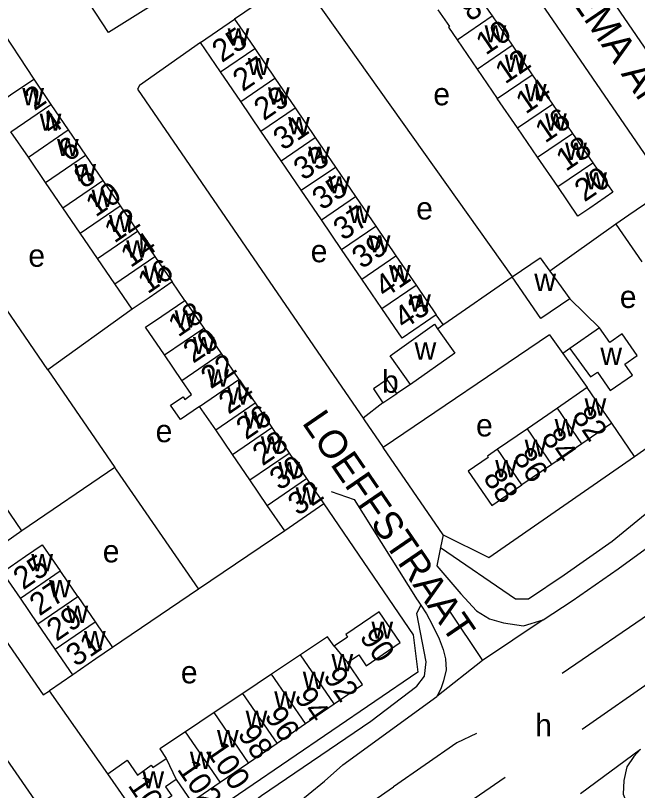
# Model space of a CAD drawing. Extents: x 157569 to 159501, y 382907 to 384670.
# Drawn here: x 158257.4 to 158368.1, y 383461.2 to 383599.1 of the extents above; entities that cross this region are included whole.
import ezdxf

# ---------------------------------------------------------------- set-up
doc = ezdxf.new("R2010")
doc.units = 0
for name, color, linetype in [('BLT_Basislijn', 7, 'Continuous'), ('BLT_Bebouwing', 7, 'Continuous'), ('BLT_Centroide', 7, 'Continuous'), ('BLT_Huisnummer', 7, 'Continuous'), ('BLT_Huisnummer_ tussenligend', 7, 'Continuous'), ('BLT_Onderverdeling_panden', 7, 'Continuous'), ('BLT_Straatnaam', 7, 'Continuous'), ('BLT_Vlakafsluiter', 7, 'Continuous')]:
    doc.layers.add(name, color=color, linetype=linetype)

msp = doc.modelspace()

# ---------------------------------------------------------------- linework, layer by layer
at = {"layer": 'BLT_Basislijn'}
for p, q in [((158334.91, 383624.76), (158373.53, 383568.42)), ((158307.74, 383606.23), (158296.41, 383598.5)), ((158307.74, 383606.23), (158345.82, 383552.61)), ((158252.74, 383599.87), (158260.65, 383587.83)), ((158263.17, 383536.11), (158238.22, 383572.51)), ((158364.3, 383561.98), (158352.53, 383553.62)), ((158287.58, 383548.44), (158285.31, 383551.74)), ((158361.4, 383543.55), (158356.07, 383548.71)), ((158278.2, 383546.88), (158263.17, 383536.11)), ((158333.55, 383544.13), (158332.31, 383545.87)), ((158332.56, 383543.37), (158333.55, 383544.13)), ((158352.49, 383542.32), (158322.88, 383522.28)), ((158352.49, 383542.32), (158354.86, 383539)), ((158356.1, 383539.87), (158354.86, 383539)), ((158354.86, 383539), (158359.19, 383532.93)), ((158367.58, 383520.65), (158393.72, 383538.95)), ((158263.17, 383536.11), (158275.07, 383518.71)), ((158327.71, 383533.47), (158325.28, 383531.9)), ((158316.13, 383532.05), (158319.31, 383527.48)), ((158322.82, 383530.23), (158319.31, 383527.48)), ((158367.58, 383520.65), (158363.56, 383526.58)), ((158333.54, 383506.73), (158322.88, 383522.28)), ((158341.65, 383502.68), (158367.58, 383520.65)), ((158275.07, 383518.71), (158258.57, 383507.41)), ((158312.33, 383512.22), (158328.23, 383488.92)), ((158305.33, 383507.44), (158290.01, 383497.05)), ((158333.54, 383506.73), (158341.65, 383502.68)), ((158290.01, 383497.05), (158274.71, 383486.68)), ((158334.55, 383493.34), (158340.54, 383484.37)), ((158371.55, 383493.55), (158354.72, 383482.03)), ((158379.21, 383486.63), (158358.27, 383472.09)), ((158267.62, 383481.82), (158263.44, 383478.98)), ((158273.85, 383464.21), (158263.44, 383478.98)), ((158268.87, 383411.85), (158344.6, 383463.62))]:
    msp.add_line(p, q, dxfattribs=at)
for points in [[(158402.62, 383683.14), (158349.23, 383647.01), (158287.55, 383604.67), (158273.97, 383596.14), (158266.09, 383608.24)], [(158351.55, 383636.27), (158344.49, 383631.24), (158343.9, 383630.57), (158382.66, 383574.03)], [(158290.34, 383594.36), (158279.47, 383586.68), (158279.15, 383586.02), (158316.13, 383532.05)], [(158333.55, 383544.13), (158333.69, 383544.24), (158345.82, 383552.61)], [(158333.08, 383504.49), (158346.41, 383495.33), (158348.71, 383495.33), (158355.09, 383499.59), (158363.6, 383505.61), (158370.16, 383510.93), (158376.37, 383516.61), (158381.86, 383521.93), (158400.39, 383534.72)], [(158319.31, 383527.48), (158319.49, 383527.21), (158322.88, 383522.28)], [(158275.07, 383518.71), (158275.35, 383518.3), (158290.01, 383497.05)], [(158313.62, 383514.43), (158317.72, 383513.01), (158328.92, 383495.17), (158328.95, 383495.12)], [(158351.37, 383491.6), (158356.51, 383494.97), (158364.67, 383500.65), (158373.39, 383507), (158376.46, 383509.13)], [(158333.54, 383506.73), (158333.08, 383504.49)], [(158333.08, 383504.49), (158332.4, 383501.18), (158336.66, 383496.22), (158339.49, 383493.2), (158341.8, 383491.78), (158344.28, 383491.07), (158347.83, 383490.54), (158351.37, 383491.6)], [(158247.46, 383499.74), (158247.67, 383499.43), (158262.36, 383478.24), (158263.44, 383478.98)], [(158285.33, 383447.86), (158288.45, 383450.24), (158293.8, 383454.7), (158296.92, 383457.08), (158301.23, 383460.35), (158320.69, 383473.57), (158328.86, 383479.81), (158330.2, 383481.6), (158330.5, 383484.12), (158328.86, 383492.74), (158329.57, 383494.21)], [(158328.95, 383495.12), (158329.57, 383494.21)], [(158328.95, 383495.12), (158328.97, 383495.07)], [(158329.57, 383494.21), (158330.59, 383492.69), (158331.58, 383490.76), (158332.82, 383488.24), (158333.56, 383486.3), (158333.96, 383484.67), (158334.06, 383482.69), (158333.61, 383480.76), (158333.12, 383479.32), (158332.42, 383477.98)], [(158328.23, 383488.92), (158329.02, 383482.29), (158283.13, 383450.96)], [(158284.53, 383441.35), (158292.81, 383446.92), (158296.69, 383450.16), (158303.7, 383455.76), (158312.43, 383462.88), (158315.66, 383465.79), (158332.42, 383477.98)], [(158251.08, 383470.55), (158252.5, 383471.5), (158264.68, 383454)], [(158339.47, 383471.34), (158335.98, 383469.7), (158324.71, 383461.89)], [(158368.7, 383468.6), (158367.49, 383467.29), (158366.26, 383465.41), (158365.68, 383463.03), (158365.61, 383460.57), (158366.26, 383458.9), (158367.85, 383456.37), (158370.74, 383452.03), (158372.62, 383449.93), (158373.85, 383448.78)], [(158262.9, 383417.82), (158318.11, 383457.34), (158324.71, 383461.89)]]:
    msp.add_lwpolyline(points, dxfattribs=at)
at = {"layer": 'BLT_Bebouwing'}
for p, q in [((158338.66, 383604.29), (158342.24, 383599.07)), ((158342.24, 383599.07), (158345.83, 383593.84)), ((158290.34, 383594.36), (158296.41, 383598.5)), ((158336.02, 383594.83), (158339.6, 383589.6)), ((158293.93, 383589.09), (158290.34, 383594.36)), ((158345.83, 383593.84), (158349.41, 383588.61)), ((158300, 383593.24), (158303.59, 383587.97)), ((158339.6, 383589.6), (158343.18, 383584.37)), ((158297.52, 383583.83), (158293.93, 383589.09)), ((158303.59, 383587.97), (158307.18, 383582.71)), ((158349.41, 383588.61), (158353, 383583.38)), ((158260.65, 383587.83), (158263.73, 383583.32)), ((158301.11, 383578.57), (158297.52, 383583.83)), ((158346.77, 383579.14), (158343.18, 383584.37)), ((158263.73, 383583.32), (158266.81, 383578.81)), ((158307.18, 383582.71), (158310.77, 383577.45)), ((158353, 383583.38), (158356.58, 383578.16)), ((158259.7, 383573.95), (158256.61, 383578.46)), ((158266.81, 383578.81), (158269.9, 383574.3)), ((158304.7, 383573.3), (158301.11, 383578.57)), ((158350.35, 383573.92), (158346.77, 383579.14)), ((158310.77, 383577.45), (158314.36, 383572.18)), ((158356.58, 383578.16), (158360.17, 383572.93)), ((158269.9, 383574.3), (158272.98, 383569.79)), ((158262.78, 383569.43), (158259.7, 383573.95)), ((158308.29, 383568.04), (158304.7, 383573.3)), ((158353.93, 383568.69), (158350.35, 383573.92)), ((158314.36, 383572.18), (158317.95, 383566.92)), ((158265.86, 383564.92), (158262.78, 383569.43)), ((158272.98, 383569.79), (158276.06, 383565.28)), ((158311.88, 383562.78), (158308.29, 383568.04)), ((158317.95, 383566.92), (158321.54, 383561.66)), ((158268.95, 383560.41), (158265.86, 383564.92)), ((158276.06, 383565.28), (158279.15, 383560.76)), ((158315.47, 383557.52), (158311.88, 383562.78)), ((158364.3, 383561.98), (158368.89, 383555.28)), ((158272.03, 383555.9), (158268.95, 383560.41)), ((158279.15, 383560.76), (158282.23, 383556.25)), ((158321.54, 383561.66), (158325.13, 383556.4)), ((158282.23, 383556.25), (158285.31, 383551.74)), ((158319.06, 383552.25), (158315.47, 383557.52)), ((158325.13, 383556.4), (158328.72, 383551.13)), ((158275.11, 383551.39), (158272.03, 383555.9)), ((158352.53, 383553.62), (158356.07, 383548.71)), ((158322.65, 383546.99), (158319.06, 383552.25)), ((158278.2, 383546.88), (158275.11, 383551.39)), ((158328.72, 383551.13), (158332.31, 383545.87)), ((158287.58, 383548.44), (158290.93, 383543.53)), ((158290.93, 383543.53), (158294.05, 383538.97)), ((158361.4, 383543.55), (158356.1, 383539.87)), ((158287.05, 383534.19), (158283.93, 383538.75)), ((158294.05, 383538.97), (158297.19, 383534.37)), ((158327.71, 383533.47), (158324.09, 383538.6)), ((158297.19, 383534.37), (158300.05, 383530.19)), ((158325.28, 383531.9), (158323.6, 383534.38)), ((158359.19, 383532.93), (158353.87, 383529.28)), ((158322.82, 383530.23), (158325.28, 383531.9)), ((158300.05, 383530.19), (158303.05, 383525.8)), ((158293.05, 383525.41), (158290.19, 383529.59)), ((158353.87, 383529.28), (158348.54, 383525.61)), ((158363.56, 383526.58), (158358.23, 383522.92)), ((158296.05, 383521.02), (158293.05, 383525.41)), ((158303.05, 383525.8), (158306.14, 383521.27)), ((158348.54, 383525.61), (158343.2, 383521.95)), ((158358.23, 383522.92), (158352.9, 383519.26)), ((158299.15, 383516.49), (158296.05, 383521.02)), ((158306.14, 383521.27), (158309.24, 383516.75)), ((158352.9, 383519.26), (158347.57, 383515.6)), ((158302.24, 383511.97), (158299.15, 383516.49)), ((158309.24, 383516.75), (158312.33, 383512.22)), ((158258.57, 383507.41), (158255.5, 383511.89)), ((158305.33, 383507.44), (158302.24, 383511.97)), ((158258.28, 383495.46), (158255.1, 383500.1)), ((158268.49, 383495.77), (158271.6, 383491.23)), ((158261.39, 383490.91), (158258.28, 383495.46)), ((158264.5, 383486.37), (158261.39, 383490.91)), ((158271.6, 383491.23), (158274.71, 383486.68)), ((158267.62, 383481.82), (158264.5, 383486.37)), ((158308.12, 383485.35), (158303.01, 383481.93)), ((158303.01, 383481.93), (158297.89, 383478.51)), ((158297.89, 383478.51), (158292.77, 383475.1)), ((158309.05, 383473.13), (158314.12, 383476.62)), ((158292.77, 383475.1), (158287.65, 383471.68)), ((158303.97, 383469.65), (158309.05, 383473.13)), ((158298.9, 383466.17), (158303.97, 383469.65)), ((158293.82, 383462.68), (158298.9, 383466.17)), ((158279.37, 383456.24), (158273.85, 383464.21))]:
    msp.add_line(p, q, dxfattribs=at)
for points in [[(158332.61, 383600.17), (158334.66, 383597.18), (158334.49, 383597.06), (158336.02, 383594.83)], [(158296.41, 383598.5), (158299.23, 383594.37), (158300, 383593.24)], [(158253.53, 383582.97), (158256.52, 383585.01), (158260.65, 383587.83)], [(158360.17, 383572.93), (158363.75, 383567.7), (158359.63, 383564.87), (158357.52, 383563.46), (158353.93, 383568.69)], [(158370.7, 383566.41), (158366.58, 383563.59), (158364.3, 383561.98)], [(158345.82, 383552.61), (158350.82, 383556.01), (158352.53, 383553.62)], [(158356.07, 383548.71), (158350.93, 383545.24), (158345.82, 383552.61)], [(158285.31, 383551.74), (158281.18, 383548.92), (158278.2, 383546.88)], [(158283.93, 383538.75), (158280.58, 383543.66), (158283.45, 383545.62), (158287.58, 383548.44)], [(158332.31, 383545.87), (158330.37, 383544.55), (158326.24, 383541.73), (158322.65, 383546.99)], [(158324.09, 383538.6), (158331.98, 383544.2), (158332.56, 383543.37)], [(158332.56, 383543.37), (158335.61, 383539.05), (158327.71, 383533.47)], [(158363.29, 383532.43), (158367.23, 383535.16), (158365.87, 383537.12), (158368.05, 383538.63), (158365.39, 383542.47), (158363.2, 383540.95), (158361.4, 383543.55)], [(158356.1, 383539.87), (158359.78, 383534.83), (158361.02, 383535.69), (158363.29, 383532.43)], [(158290.19, 383529.59), (158286.76, 383527.24), (158285.03, 383529.77), (158287.24, 383531.28), (158287.55, 383530.83), (158288.77, 383531.67), (158287.05, 383534.19)], [(158323.6, 383534.38), (158321.14, 383532.71), (158322.82, 383530.23)], [(158363.56, 383526.58), (158360.73, 383530.7), (158359.19, 383532.93)], [(158343.2, 383521.95), (158341.43, 383520.73), (158341.57, 383520.5), (158338.02, 383518.06), (158342.23, 383511.93), (158347.57, 383515.6)], [(158312.33, 383512.22), (158305.33, 383507.44)], [(158258.57, 383507.41), (158255.68, 383505.43), (158251.56, 383502.6)], [(158255.1, 383500.1), (158259.22, 383502.93), (158262.19, 383504.96), (158265.38, 383500.32)], [(158268.49, 383495.77), (158265.59, 383500), (158265.38, 383500.32)], [(158316.52, 383483.98), (158318.53, 383485.36), (158319.85, 383483.42), (158325.9, 383487.57), (158322.13, 383493.05), (158316.19, 383488.97), (158316.5, 383488.52), (158314.15, 383486.9)], [(158314.15, 383486.9), (158312.98, 383488.6), (158308.12, 383485.35)], [(158274.71, 383486.68), (158271.74, 383484.65), (158267.62, 383481.82)], [(158314.12, 383476.62), (158319.19, 383480.1), (158316.52, 383483.98)], [(158287.65, 383471.68), (158283.09, 383468.63), (158284.25, 383466.93)], [(158273.85, 383464.21), (158277.32, 383466.64), (158279.16, 383463.96), (158281.58, 383465.76), (158281.89, 383465.31), (158284.25, 383466.93)], [(158286.02, 383463.18), (158284.12, 383461.87), (158285.22, 383460.25), (158279.37, 383456.24)], [(158286.02, 383463.18), (158288.75, 383459.2), (158293.82, 383462.68)]]:
    msp.add_lwpolyline(points, dxfattribs=at)
at = {"layer": 'BLT_Onderverdeling_panden'}
for p, q in [((158336.02, 383594.83), (158342.24, 383599.07)), ((158339.6, 383589.6), (158345.83, 383593.84)), ((158293.93, 383589.09), (158300, 383593.24)), ((158297.52, 383583.83), (158303.59, 383587.97)), ((158343.18, 383584.37), (158349.41, 383588.61)), ((158256.61, 383578.46), (158263.73, 383583.32)), ((158301.11, 383578.57), (158307.18, 383582.71)), ((158346.77, 383579.14), (158353, 383583.38)), ((158259.7, 383573.95), (158266.81, 383578.81)), ((158304.7, 383573.3), (158310.77, 383577.45)), ((158350.35, 383573.92), (158356.58, 383578.16)), ((158262.78, 383569.43), (158269.9, 383574.3)), ((158353.93, 383568.69), (158360.17, 383572.93)), ((158308.29, 383568.04), (158314.36, 383572.18)), ((158265.86, 383564.92), (158272.98, 383569.79)), ((158311.88, 383562.78), (158317.95, 383566.92)), ((158268.95, 383560.41), (158276.06, 383565.28)), ((158272.03, 383555.9), (158279.15, 383560.76)), ((158315.47, 383557.52), (158321.54, 383561.66)), ((158275.11, 383551.39), (158282.23, 383556.25)), ((158319.06, 383552.25), (158325.13, 383556.4)), ((158322.65, 383546.99), (158328.72, 383551.13)), ((158283.93, 383538.75), (158290.93, 383543.53)), ((158287.05, 383534.19), (158294.05, 383538.97)), ((158290.19, 383529.59), (158297.19, 383534.37)), ((158293.05, 383525.41), (158300.05, 383530.19)), ((158358.23, 383522.92), (158353.87, 383529.28)), ((158296.05, 383521.02), (158303.05, 383525.8)), ((158352.9, 383519.26), (158348.54, 383525.61)), ((158347.57, 383515.6), (158343.2, 383521.95)), ((158299.15, 383516.49), (158306.14, 383521.27)), ((158302.24, 383511.97), (158309.24, 383516.75)), ((158258.28, 383495.46), (158265.38, 383500.32)), ((158261.39, 383490.91), (158268.49, 383495.77)), ((158264.5, 383486.37), (158271.6, 383491.23)), ((158314.15, 383486.9), (158316.52, 383483.98)), ((158314.12, 383476.62), (158308.12, 383485.35)), ((158309.05, 383473.13), (158303.01, 383481.93)), ((158303.97, 383469.65), (158297.89, 383478.51)), ((158298.9, 383466.17), (158292.77, 383475.1)), ((158293.82, 383462.68), (158287.65, 383471.68)), ((158284.25, 383466.93), (158286.02, 383463.18))]:
    msp.add_line(p, q, dxfattribs=at)
at = {"layer": 'BLT_Vlakafsluiter'}
for p, q in [((158351.37, 383491.6), (158340.54, 383484.37)), ((158340.54, 383484.37), (158332.42, 383477.98)), ((158358.02, 383460.71), (158368.7, 383468.6))]:
    msp.add_line(p, q, dxfattribs=at)

# ---------------------------------------------------------------- texts
at = {"layer": 'BLT_Centroide'}
for s, p in [('w', (158295.17, 383593.78)), ('w', (158340.92, 383594.34)), ('w', (158344.51, 383589.09)), ('w', (158298.76, 383588.53)), ('w', (158348.09, 383583.88)), ('w', (158258.62, 383583.16)), ('w', (158302.35, 383583.28)), ('e', (158331.79, 383583.16)), ('w', (158261.72, 383578.62)), ('w', (158305.94, 383578)), ('w', (158351.68, 383578.66)), ('w', (158264.8, 383574.12)), ('w', (158309.53, 383572.75)), ('w', (158355.26, 383573.44)), ('w', (158267.88, 383569.62)), ('w', (158313.12, 383567.47)), ('w', (158358.84, 383568.19)), ('w', (158270.96, 383565.09)), ('e', (158328.74, 383562.84)), ('w', (158316.71, 383562.22)), ('w', (158274.05, 383560.59)), ('w', (158277.12, 383556.06)), ('w', (158320.3, 383556.97)), ('e', (158309.96, 383555.23)), ('e', (158259.7, 383554.43)), ('w', (158280.21, 383551.56)), ('w', (158323.89, 383551.69)), ('w', (158349.77, 383550.1)), ('w', (158327.48, 383546.44)), ('e', (158364.99, 383547.09)), ('w', (158285.76, 383543.59)), ('w', (158288.99, 383538.88)), ('w', (158328.45, 383537.89)), ('w', (158361.53, 383536.97)), ('w', (158291.56, 383533.09)), ('b', (158322.66, 383532.01)), ('w', (158295.12, 383529.91)), ('w', (158358.72, 383527.94)), ('w', (158298.05, 383525.59)), ('e', (158339.4, 383524.24)), ('w', (158353.39, 383524.27)), ('e', (158282.36, 383523.21)), ('w', (158301.09, 383521.16)), ('w', (158348.05, 383520.61)), ('w', (158304.19, 383516.62)), ('w', (158342.8, 383516.98)), ('w', (158307.28, 383512.09)), ('e', (158272.95, 383501.82)), ('w', (158260.23, 383500.22)), ('w', (158263.39, 383495.62)), ('w', (158266.5, 383491.06)), ('w', (158320.77, 383488.22)), ('w', (158269.61, 383486.53)), ('w', (158313.66, 383482.44)), ('e', (158286.85, 383480.29)), ('w', (158308.56, 383479.28)), ('w', (158303.47, 383475.81)), ('w', (158298.38, 383472.38)), ('h', (158349.92, 383470.84)), ('w', (158293.28, 383468.92)), ('w', (158288.45, 383465.06)), ('w', (158280.01, 383461.59))]:
    msp.add_text(s, height=4, dxfattribs=at).set_placement(p)
at = {"layer": 'BLT_Huisnummer'}
for s, rotation, p in [('10', 34.2427, (158341.12, 383591.98)), ('25', 34.2998, (158294.16, 383590.65)), ('2', 34.3466, (158260.78, 383582.09)), ('14', 34.2427, (158348.23, 383581.49)), ('29', 34.2998, (158301.62, 383580.31)), ('6', 34.3466, (158266.81, 383572.97)), ('33', 34.2998, (158308.67, 383569.67)), ('20', 34.2427, (158358.69, 383565.86)), ('10', 34.3466, (158271.69, 383563.17)), ('37', 34.2998, (158315.75, 383558.96)), ('16', 34.3466, (158280.95, 383549.5)), ('43', 34.2998, (158326.56, 383543.18)), ('18', 34.3483, (158286.37, 383541.8)), ('22', 34.3483, (158292.17, 383532.58)), ('26', 34.3483, (158298.46, 383523.51)), ('82', 304.4817, (158356.37, 383527.91)), ('88', 304.4831, (158340.53, 383516.86)), ('32', 34.3483, (158307.68, 383510.01)), ('25', 34.4568, (158258.78, 383496.81)), ('90', 304.4684, (158318.55, 383488.55)), ('31', 34.4568, (158268.17, 383483.13)), ('94', 304.4687, (158306.9, 383477.92)), ('98', 304.4693, (158296.83, 383471.26)), ('104', 304.4625, (158277.31, 383462.14))]:
    msp.add_text(s, height=4, rotation=rotation, dxfattribs=at).set_placement(p)
at = {"layer": 'BLT_Huisnummer_ tussenligend'}
for s, rotation, p in [('8', 34.2427, (158338.38, 383597.95)), ('12', 34.2427, (158344.57, 383586.83)), ('27', 34.2998, (158297.86, 383585.48)), ('16', 34.2427, (158351.68, 383576.33)), ('4', 34.3466, (158263.68, 383577.72)), ('31', 34.2998, (158305.05, 383575.01)), ('18', 34.2427, (158355.39, 383571.3)), ('8', 34.3466, (158269.59, 383568.21)), ('35', 34.2998, (158311.98, 383564.37)), ('12', 34.3466, (158275.01, 383558.54)), ('14', 34.3466, (158277.9, 383554.17)), ('39', 34.2998, (158319.07, 383553.93)), ('41', 34.2998, (158323.15, 383548.76)), ('20', 34.3483, (158289.04, 383537.13)), ('24', 34.3483, (158295.34, 383528.07)), ('28', 34.3483, (158301.38, 383518.89)), ('84', 304.4817, (158350.93, 383524.08)), ('86', 304.4817, (158345.84, 383520.55)), ('30', 34.3483, (158304.42, 383514.51)), ('27', 34.4568, (158261.68, 383492.17)), ('29', 34.4568, (158264.73, 383487.67)), ('92', 304.4684, (158312.07, 383481.53)), ('96', 304.4687, (158301.61, 383474.48)), ('100', 304.4693, (158291.11, 383468.32)), ('102', 304.4693, (158286.08, 383465))]:
    msp.add_text(s, height=4, rotation=rotation, dxfattribs=at).set_placement(p)
at = {"layer": 'BLT_Straatnaam'}
for s, rotation, p in [('FOCKEMA ANDREAESTRAAT', 304.2254, (158345.47, 383617.62)), ('LOEFFSTRAAT', 304.3957, (158308.3, 383526.66))]:
    msp.add_text(s, height=5, rotation=rotation, dxfattribs=at).set_placement(p)

doc.saveas('drawing.dxf')
